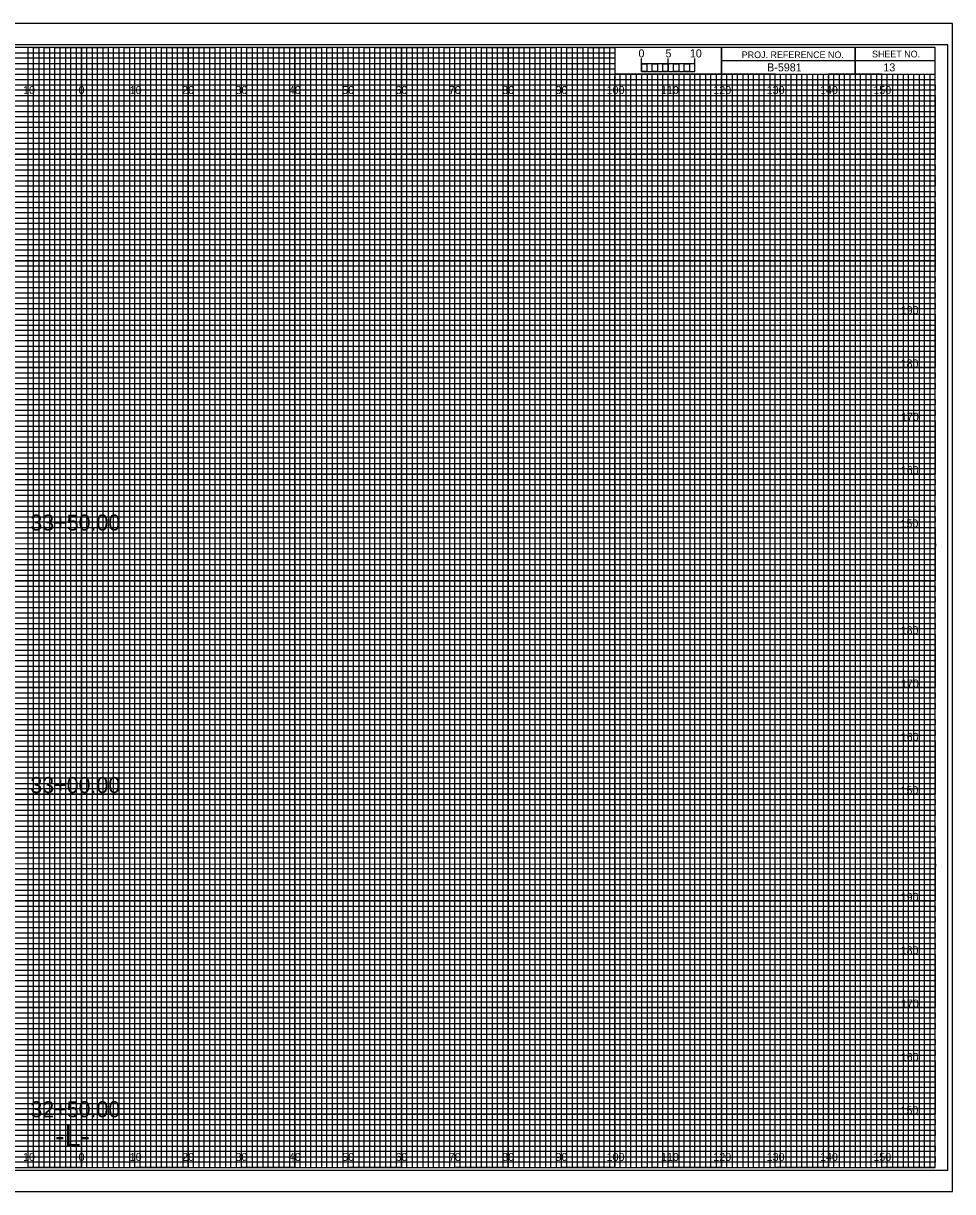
# Model space of a CAD drawing. Extents: x -13 to 323, y -5 to 434.
# Drawn here: x 149.1 to 323.3, y 215.5 to 434.5 of the extents above; entities that cross this region are included whole.
import ezdxf

# ---------------------------------------------------------------- set-up
doc = ezdxf.new("R2010")
doc.units = 0
for name, color, linetype in [('Exist Cross Section Cell', 7, 'Continuous'), ('Exist XS Center Line Elevation Label', 7, 'Continuous'), ('Exist XS Ground Line', 7, 'Continuous'), ('Prop CMT Concrete Structures', 7, 'Continuous'), ('Prop CMT Guardrail Graphics', 7, 'Continuous'), ('Prop CMT Pvmt Course 1', 7, 'Continuous'), ('Prop CMT Pvmt Course 2', 7, 'Continuous'), ('Prop CMT Pvmt Course 3', 7, 'Continuous'), ('Prop CMT Pvmt Surface', 7, 'Continuous'), ('Prop CMT Shld Paved Course 1', 7, 'Continuous'), ('Prop CMT Shld Paved Course 2', 7, 'Continuous'), ('Prop CMT Shld Paved Course 3', 7, 'Continuous'), ('Prop CMT Subgrade Earthwork', 7, 'Continuous'), ('Prop XS Ditch Standard Text', 7, 'Continuous'), ('Prop XS SE Text', 7, 'Continuous'), ('Prop XS Side Slope Text', 7, 'Continuous'), ('Scratch_Level_0', 7, 'Continuous')]:
    doc.layers.add(name, color=color, linetype=linetype)

msp = doc.modelspace()

# ---------------------------------------------------------------- linework, layer by layer
at = {"layer": 'Exist XS Center Line Elevation Label'}
for points in [[(145, 220), (155, 220), (155, 430), (165, 430), (165, 220), (175, 220), (175, 430), (185, 430), (185, 220), (195, 220), (195, 430), (205, 430), (205, 220), (215, 220), (215, 430), (225, 430), (225, 220), (235, 220), (235, 430), (245, 430), (245, 220), (255, 220), (255, 430), (259.93, 430), (260, 430), (260, 425), (264.99, 425), (264.99, 220), (275, 220), (275, 425), (285, 425), (285, 220), (295, 220), (295, 425), (305, 425), (305, 220), (315, 220), (315, 425)], [(0, 425), (275, 425)], [(0, 405), (320, 405), (320, 415), (0, 415)], [(0, 385), (320, 385), (320, 395), (0, 395)], [(0, 365), (320, 365), (320, 375), (0, 375)], [(0, 345), (320, 345), (320, 355), (0, 355)], [(0, 325), (320, 325), (320, 335), (0, 335)], [(0, 305), (320, 305), (320, 315), (0, 315)], [(0, 285), (320, 285), (320, 295), (0, 295)], [(0, 265), (320, 265), (320, 275), (0, 275)], [(0, 245), (320, 245), (320, 255), (0, 255)], [(0, 225), (320, 225), (320, 235), (0, 235)]]:
    msp.add_lwpolyline(points, dxfattribs=at)
at = {"layer": 'Exist XS Ground Line'}
for p, q in [((150, 430), (140, 430)), ((150, 220), (150, 430)), ((170, 430), (160, 430)), ((160, 430), (160, 220)), ((170, 220), (170, 430)), ((190, 430), (180, 430)), ((180, 430), (180, 220)), ((190, 220), (190, 430)), ((210, 430), (200, 430)), ((200, 430), (200, 220)), ((210, 220), (210, 430)), ((230, 430), (220, 430)), ((220, 430), (220, 220)), ((230, 220), (230, 430)), ((250, 430), (240, 430)), ((240, 430), (240, 220)), ((250, 220), (250, 430)), ((260, 430), (260, 220)), ((270, 220), (270, 425)), ((290, 425), (280, 425)), ((280, 425), (280, 220)), ((290, 220), (290, 425)), ((310, 425), (300, 425)), ((300, 425), (300, 220)), ((310, 220), (310, 425)), ((160, 220), (150, 220)), ((180, 220), (170, 220)), ((200, 220), (190, 220)), ((220, 220), (210, 220)), ((240, 220), (230, 220)), ((260, 220), (250, 220)), ((280, 220), (270, 220)), ((300, 220), (290, 220)), ((320, 220), (310, 220)), ((320, 220), (320, 220))]:
    msp.add_line(p, q, dxfattribs=at)
for points in [[(0, 420), (320, 420), (320, 410), (0, 410)], [(0, 400), (320, 400), (320, 390), (0, 390)], [(0, 380), (320, 380), (320, 370), (0, 370)], [(0, 360), (320, 360), (320, 350), (0, 350)], [(0, 340), (320, 340), (320, 330), (0, 330)], [(0, 320), (320, 320), (320, 310), (0, 310)], [(0, 300), (320, 300), (320, 290), (0, 290)], [(0, 280), (320, 280), (320, 270), (0, 270)], [(0, 260), (320, 260), (320, 250), (0, 250)], [(0, 240), (320, 240), (320, 230), (0, 230)]]:
    msp.add_lwpolyline(points, dxfattribs=at)
at = {"layer": 'Prop CMT Pvmt Course 1'}
for p, q in [((323.3, 434.5), (-13.4, 434.5)), ((-13.4, 215.5), (323.3, 215.5))]:
    msp.add_line(p, q, dxfattribs=at)
at = {"layer": 'Prop CMT Pvmt Course 2'}
msp.add_lwpolyline([(-13.4, 215.5), (323.3, 215.5), (323.3, 434.5), (-13.4, 434.5)], close=True, dxfattribs=at)
at = {"layer": 'Prop CMT Pvmt Course 3'}
msp.add_lwpolyline([(-10.8, 219.5), (322.4, 219.5), (322.4, 430.5), (-10.8, 430.5)], close=True, dxfattribs=at)
at = {"layer": 'Prop CMT Shld Paved Course 1'}
for p, q in [((305, 430), (305, 425)), ((305, 425), (305, 430)), ((280, 427.5), (280, 425)), ((320, 427.49), (280, 427.49)), ((280, 425), (320, 425))]:
    msp.add_line(p, q, dxfattribs=at)
for points in [[(320, 430), (0, 430), (0, 220), (320, 220)], [(280, 430), (260, 430), (260, 425.03), (280, 425.03)], [(320, 430), (280, 430), (280, 425), (320, 425)]]:
    msp.add_lwpolyline(points, close=True, dxfattribs=at)
at = {"layer": 'Prop CMT Shld Paved Course 2'}
for p, q in [((267, 425), (266.01, 425)), ((266.01, 425), (266.01, 220)), ((267, 220), (267, 425)), ((269, 425), (268, 425)), ((268, 425), (268, 220)), ((269, 220), (269, 425)), ((266.01, 220), (265, 220)), ((268, 220), (267, 220))]:
    msp.add_line(p, q, dxfattribs=at)
for points in [[(150, 220), (151, 220), (151, 430), (152, 430), (152, 220)], [(152, 220), (153, 220), (153, 430), (154, 430), (154, 220)], [(155, 220), (156, 220), (156, 430), (157, 430), (157, 220)], [(157, 220), (158, 220), (158, 430), (159, 430), (159, 220)], [(160, 220), (161, 220), (161, 430), (162, 430), (162, 220)], [(162, 220), (163, 220), (163, 430), (164, 430), (164, 220)], [(165, 220), (166, 220), (166, 430), (167, 430), (167, 220)], [(167, 220), (168, 220), (168, 430), (169, 430), (169, 220)], [(170, 220), (171, 220), (171, 430), (172, 430), (172, 220)], [(172, 220), (173, 220), (173, 430), (174, 430), (174, 220)], [(175, 220), (176, 220), (176, 430), (177, 430), (177, 220)], [(177, 220), (178, 220), (178, 430), (179, 430), (179, 220)], [(180, 220), (181, 220), (181, 430), (182, 430), (182, 220)], [(182, 220), (183, 220), (183, 430), (184, 430), (184, 220)], [(185, 220), (186, 220), (186, 430), (187, 430), (187, 220)], [(187, 220), (188, 220), (188, 430), (189, 430), (189, 220)], [(190, 220), (191, 220), (191, 430), (192, 430), (192, 220)], [(192, 220), (193, 220), (193, 430), (194, 430), (194, 220)], [(195, 220), (196, 220), (196, 430), (197, 430), (197, 220)], [(197, 220), (198, 220), (198, 430), (199, 430), (199, 220)], [(200, 220), (201, 220), (201, 430), (202, 430), (202, 220)], [(202, 220), (203, 220), (203, 430), (204, 430), (204, 220)], [(205, 220), (206, 220), (206, 430), (207, 430), (207, 220)], [(207, 220), (208, 220), (208, 430), (209, 430), (209, 220)], [(210, 220), (211, 220), (211, 430), (212, 430), (212, 220)], [(212, 220), (213, 220), (213, 430), (214, 430), (214, 220)], [(215, 220), (216, 220), (216, 430), (217, 430), (217, 220)], [(217, 220), (218, 220), (218, 430), (219, 430), (219, 220)], [(220, 220), (221, 220), (221, 430), (222, 430), (222, 220)], [(222, 220), (223, 220), (223, 430), (224, 430), (224, 220)], [(225, 220), (226, 220), (226, 430), (227, 430), (227, 220)], [(227, 220), (228, 220), (228, 430), (229, 430), (229, 220)], [(230, 220), (231, 220), (231, 430), (232, 430), (232, 220)], [(232, 220), (233, 220), (233, 430), (234, 430), (234, 220)], [(235, 220), (236, 220), (236, 430), (237, 430), (237, 220)], [(237, 220), (238, 220), (238, 430), (239, 430), (239, 220)], [(240, 220), (241, 220), (241, 430), (242, 430), (242, 220)], [(242, 220), (243, 220), (243, 430), (244, 430), (244, 220)], [(245, 220), (246, 220), (246, 430), (247, 430), (247, 220)], [(247, 220), (248, 220), (248, 430), (249, 430), (249, 220)], [(250, 220), (251, 220), (251, 430), (252, 430), (252, 220)], [(252, 220), (253, 220), (253, 430), (254, 430), (254, 220)], [(255, 220), (256, 220), (256, 430), (257, 430), (257, 220)], [(257, 220), (258, 220), (258, 430), (259, 430), (259, 220)], [(260, 220), (261, 220), (261, 425), (262.02, 425), (262.02, 220)], [(262, 220), (263, 220), (263, 425), (263.99, 425), (263.99, 220)], [(270, 220), (270.98, 220), (270.98, 425), (272, 425), (272, 220)], [(272, 220), (273, 220), (273, 425), (274.05, 425), (274.05, 220)], [(275, 220), (276, 220), (276, 425), (277, 425), (277, 220)], [(277, 220), (278, 220), (278, 425), (279, 425), (279, 220)], [(280, 220), (281, 220), (281, 425), (282, 425), (282, 220)], [(282, 220), (283, 220), (283, 425), (284, 425), (284, 220)], [(285, 220), (286, 220), (286, 425), (287, 425), (287, 220)], [(287, 220), (288, 220), (288, 425), (289, 425), (289, 220)], [(290, 220), (291, 220), (291, 425), (292, 425), (292, 220)], [(292, 220), (293, 220), (293, 425), (294, 425), (294, 220)], [(295, 220), (296, 220), (296, 425), (297, 425), (297, 220)], [(297, 220), (298, 220), (298, 425), (299, 425), (299, 220)], [(300, 220), (301, 220), (301, 425), (302, 425), (302, 220)], [(302, 220), (303, 220), (303, 425), (304, 425), (304, 220)], [(305, 220), (306, 220), (306, 425), (307, 425), (307, 220)], [(307, 220), (308, 220), (308, 425), (309, 425), (309, 220)], [(310, 220), (311, 220), (311, 425), (312, 425), (312, 220)], [(312, 220), (313, 220), (313, 425), (314, 425), (314, 220)], [(315, 220), (316, 220), (316, 425), (317, 425), (317, 220)], [(317, 220), (318, 220), (318, 425), (319, 425), (319, 220)]]:
    msp.add_lwpolyline(points, dxfattribs=at)
at = {"layer": 'Prop CMT Shld Paved Course 3'}
for p, q in [((265, 425.49), (265, 427.9)), ((265, 426.9), (265, 427.9)), ((270, 425.49), (270, 427.9)), ((275, 425.49), (275, 427.9)), ((275, 426.9), (275, 427.9))]:
    msp.add_line(p, q, dxfattribs=at)
for points in [[(275, 426.9), (265, 426.9), (265, 425.49), (275, 425.49)], [(265, 426.9), (266, 426.9), (266, 425.49), (265, 425.49)], [(267, 426.9), (268, 426.9), (268, 425.49), (267, 425.49)], [(269, 426.9), (270, 426.9), (270, 425.49), (269, 425.49)], [(271, 426.9), (272, 426.9), (272, 425.49), (271, 425.49)], [(273, 426.9), (274, 426.9), (274, 425.49), (273, 425.49)]]:
    msp.add_lwpolyline(points, close=True, dxfattribs=at)
at = {"layer": 'Prop CMT Subgrade Earthwork'}
for p, q in [((150, 220), (150, 430)), ((160, 220), (160, 430)), ((170, 220), (170, 430)), ((180, 220), (180, 430)), ((190, 220), (190, 430)), ((200, 220), (200, 430)), ((210, 220), (210, 430)), ((220, 220), (220, 430)), ((230, 220), (230, 430)), ((240, 220), (240, 430)), ((250, 220), (250, 430)), ((260, 220), (260, 424.69)), ((270, 220), (270, 424.69)), ((280, 220), (280, 424.69)), ((290, 220), (290, 424.69)), ((300, 220), (300, 424.69)), ((310, 220), (310, 424.69)), ((0, 420), (320, 420)), ((0, 410), (320, 410)), ((0, 400), (320, 400)), ((0, 390), (320, 390)), ((0, 380), (320, 380)), ((0, 370), (320, 370)), ((0, 360), (320, 360)), ((0, 350), (320, 350)), ((0, 340), (320, 340)), ((0, 330), (320, 330)), ((0, 320), (320, 320)), ((0, 310), (320, 310)), ((0, 300), (320, 300)), ((0, 290), (320, 290)), ((0, 280), (320, 280)), ((0, 270), (320, 270)), ((0, 260), (320, 260)), ((0, 250), (320, 250)), ((0, 240), (320, 240)), ((0, 230), (320, 230))]:
    msp.add_line(p, q, dxfattribs=at)
at = {"layer": 'Scratch_Level_0'}
for p, q in [((0, 429), (260, 429)), ((260, 427.98), (0, 427.98)), ((260, 429), (260, 427.98)), ((0, 427), (260, 427)), ((260, 425.89), (0, 425.89)), ((260, 427), (260, 425.89)), ((0, 424), (320, 424))]:
    msp.add_line(p, q, dxfattribs=at)
for points in [[(0, 423), (270, 423), (320, 423), (320, 422), (0, 422)], [(0, 421), (320, 421), (320, 419), (0, 419)], [(0, 418), (320, 418), (320, 417), (0, 416.98)], [(0, 416), (320, 416), (320, 414), (0, 414)], [(0, 413), (320, 413), (320, 412), (0, 412)], [(0, 411), (320, 411), (320, 409), (0, 409)], [(0, 408), (320, 408), (320, 407), (0, 407)], [(0, 406), (320, 406), (320, 404), (0, 404)], [(0, 403), (320, 403), (320, 402), (0, 402)], [(0, 401), (320, 401), (320, 399), (0, 399)], [(0, 398), (320, 398), (320, 397), (0, 397)], [(0, 396), (320, 396), (320, 393.95), (320, 393), (320, 392), (0, 392)], [(0, 394), (320, 394), (320, 393), (0, 393)], [(0, 391), (320, 391), (320, 389), (0, 389.03)], [(0, 389.03), (320, 389), (320, 388), (0, 388)], [(0, 387), (320, 387), (320, 386), (0, 386)], [(0, 384), (320, 384), (320, 383), (0, 383)], [(0, 382), (320, 382), (320, 381), (0, 381)], [(-0.07, 378.89), (320, 378.89), (320, 377.88), (-0.07, 377.88)], [(0, 377), (320, 377), (320, 376), (0, 376)], [(0, 374), (320, 374), (320, 373), (0, 373)], [(0, 372), (320, 372), (320, 371), (0, 371)], [(0, 369), (320, 369), (320, 368), (0, 368)], [(0, 367), (320, 367), (320, 366), (0, 366)], [(0, 364), (320, 364), (320, 363), (0, 363)], [(0, 362), (320, 362), (320, 361), (0, 361)], [(0, 359), (320, 359), (319.99, 357.98), (0, 358)], [(0, 357), (320, 357), (320, 356), (0, 356)], [(0, 354), (320, 354), (320, 353), (0, 353)], [(0, 352), (320, 352), (320, 351), (0, 351)], [(0, 349), (320, 349), (320, 348), (0, 348)], [(0, 347), (320, 347), (320, 346), (0, 346)], [(0, 344), (320, 344), (320, 343), (0, 343)], [(0, 342), (320, 342), (320, 341), (0, 341)], [(0, 339), (320, 339), (320, 338), (0, 338)], [(0, 336.99), (320.07, 336.91), (320, 336), (0, 336)], [(0, 334), (320, 334), (320, 333), (0, 333)], [(0, 332), (320, 332), (320, 331), (0, 331)], [(0, 329), (320, 329), (320, 328), (0, 328)], [(0, 327), (320, 327), (320, 326), (0, 326)], [(0, 324), (320, 324), (320, 323), (0, 323)], [(0, 322), (320, 322), (320, 321), (0, 321)], [(0, 319), (320, 319), (320, 318), (0, 318)], [(0, 317), (320, 317), (320, 316), (0, 316)], [(0, 314), (320, 314), (320, 313), (0, 313)], [(0, 312), (320, 312), (320, 311), (0, 311)], [(0, 309), (320, 309), (320, 308), (0, 308)], [(0, 307), (320, 307), (320, 306), (0, 306)], [(0, 304), (320, 304), (320, 303), (0, 303)], [(0, 302), (320, 302), (320, 301), (0, 301)], [(0, 299), (320, 299), (319.99, 297.98), (0, 298)], [(0, 297), (320, 297), (320, 296), (0, 296)], [(0, 294), (320, 294), (320, 293), (0, 293)], [(0, 292), (320, 292), (320, 291), (0, 291)], [(0, 289), (320, 289), (320, 288), (0, 288)], [(0, 287), (320, 287), (320, 286), (0, 286)], [(0, 284), (320, 284), (320, 283), (0, 283)], [(0, 282), (320, 282), (320, 281), (0, 281)], [(0, 279), (320, 279), (320, 278), (0, 278)], [(0, 276.99), (320.07, 276.91), (320, 276), (0, 276)], [(0, 274), (320, 274), (320, 273), (0, 273)], [(0, 272), (320, 272), (320, 271), (0, 271)], [(0, 269), (320, 269), (320, 268), (0, 268)], [(0, 267), (320, 267), (320, 266), (0, 266)], [(0, 264), (320, 264), (320, 263), (0, 263)], [(0, 262), (320, 262), (320, 261), (0, 261)], [(0, 259), (320, 259), (320, 258), (0, 258)], [(0, 257), (320, 257), (320, 256), (0, 256)], [(0, 254), (320, 254), (320, 253), (0, 253)], [(0, 252), (320, 252), (320, 251), (0, 251)], [(0, 249), (320, 249), (320, 248), (0, 248)], [(0, 247), (320, 247), (320, 246), (0, 246)], [(0, 244), (320, 244), (320, 243), (0, 243)], [(0, 242), (320, 242), (320, 241), (0, 241)], [(0, 239), (320, 239), (320, 238), (0, 238)], [(0, 237), (320, 237), (320, 236), (0, 236)], [(0, 234), (320, 234), (320, 233), (0, 233)], [(0, 232), (320, 232), (320, 231), (0, 231)], [(0, 229), (320, 229), (320, 228), (0, 228)], [(0, 227), (320, 227), (320, 226), (0, 226)], [(0, 224), (320, 224), (320, 223), (0, 223)], [(0, 222), (320, 222), (320, 221), (0, 221)]]:
    msp.add_lwpolyline(points, dxfattribs=at)

# ---------------------------------------------------------------- texts
at = {"layer": 'Exist Cross Section Cell'}
for s, p in [('190', (313.57, 380)), ('180', (313.55, 370)), ('170', (313.61, 360)), ('160', (313.57, 350)), ('150', (313.52, 340)), ('180', (313.55, 320)), ('170', (313.61, 310)), ('160', (313.57, 300)), ('150', (313.52, 290)), ('190', (313.57, 270)), ('180', (313.55, 260)), ('170', (313.61, 250)), ('160', (313.57, 240)), ('150', (313.52, 230))]:
    msp.add_text(s, height=1.5, dxfattribs=at).set_placement(p)
at = {"layer": 'Prop CMT Concrete Structures'}
msp.add_text('13', height=1.5, dxfattribs=at).set_placement((310.32, 425.5))
at = {"layer": 'Prop CMT Guardrail Graphics'}
for s, p in [('5', (269.47, 428.12)), ('10', (274.04, 428.12))]:
    msp.add_text(s, height=1.5, dxfattribs=at).set_placement(p)
at = {"layer": 'Prop CMT Pvmt Surface'}
for s, p in [('33+50.00', (150.41, 339.43)), ('33+00.00', (150.41, 290.22)), ('32+50.00', (150.41, 229.44))]:
    msp.add_text(s, height=3, dxfattribs=at).set_placement(p)
at = {"layer": 'Prop CMT Shld Paved Course 1'}
for s, p in [('PROJ. REFERENCE NO.', (283.77, 427.99)), ('SHEET NO.', (308.19, 428.12))]:
    msp.add_text(s, height=1.25, dxfattribs=at).set_placement(p)
at = {"layer": 'Prop CMT Shld Paved Course 3'}
msp.add_text('0', height=1.5, dxfattribs=at).set_placement((264.41, 428.12))
at = {"layer": 'Prop XS Ditch Standard Text'}
for s, p in [('10', (149.04, 421.25)), ('0', (159.45, 421.25)), ('0', (159.45, 421.25)), ('10', (169.04, 421.25)), ('20', (178.86, 421.25)), ('30', (188.86, 421.25)), ('40', (198.86, 421.25)), ('50', (208.86, 421.25)), ('60', (218.86, 421.25)), ('70', (228.86, 421.25)), ('80', (238.86, 421.25)), ('90', (248.86, 421.25)), ('100', (258.44, 421.25)), ('110', (268.62, 421.25)), ('120', (278.44, 421.25)), ('130', (288.44, 421.25)), ('140', (298.44, 421.25)), ('150', (308.44, 421.25)), ('10', (149.04, 221.25)), ('0', (159.45, 221.25)), ('0', (159.45, 221.25)), ('10', (169.04, 221.25)), ('20', (178.86, 221.25)), ('30', (188.86, 221.25)), ('40', (198.86, 221.25)), ('50', (208.86, 221.25)), ('60', (218.86, 221.25)), ('70', (228.86, 221.25)), ('80', (238.86, 221.25)), ('90', (248.86, 221.25)), ('100', (258.44, 221.25)), ('110', (268.62, 221.25)), ('120', (278.44, 221.25)), ('130', (288.44, 221.25)), ('140', (298.44, 221.25)), ('150', (308.44, 221.25))]:
    msp.add_text(s, height=1.5, dxfattribs=at).set_placement(p)
at = {"layer": 'Prop XS SE Text'}
msp.add_text('-L-', height=4, dxfattribs=at).set_placement((155.06, 224))
at = {"layer": 'Prop XS Side Slope Text'}
msp.add_text('B-5981', height=1.5, dxfattribs=at).set_placement((288.53, 425.5))

doc.saveas('drawing.dxf')
